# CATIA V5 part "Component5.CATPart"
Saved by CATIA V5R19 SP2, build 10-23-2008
Part number: Component5
Definition: Component5
Nomenclature: Component5
Source: Unknown
Bounding box of the stored display mesh (mm): x -4.283 to 0.4, y 0 to 2.367, z 0 to 3.3
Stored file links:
  Z:\fausse table rondelle-20220905T211342Z-001\fausse table rondelle\Component5.CATPart
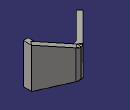
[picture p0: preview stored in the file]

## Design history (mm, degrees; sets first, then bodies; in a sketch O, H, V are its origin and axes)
AxisSystem1: origin (0, 0, 0), X (1, 0, 0), Y (0, 1, 0), Z (0, 0, 1)
Body1 "Body1" (main body)
  Solid1: solid without history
